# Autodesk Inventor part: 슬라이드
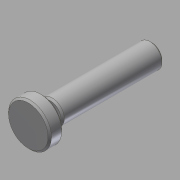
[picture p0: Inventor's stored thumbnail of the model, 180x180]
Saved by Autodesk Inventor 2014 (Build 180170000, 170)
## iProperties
Created: 2015-09
Part Number: 슬라이드
Material: 강철, 연강
Document SubType Name: Modeling
Designer: mduedu
Density: 1 g/cm^3
Appearance: Steel
Author: mduedu
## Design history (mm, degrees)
sketch "스케치1"
  geometry: C1 r 12.5 at (0, 0); 1 further point
  constraints: 1 centre point, 1 coincident
  dimensions: "d0" = 25 diameter of C1
extrude "돌출1" new body sketch "스케치1" distance "d1" = 8; taper "d2" = 0 deg
sketch "스케치2"
  geometry: C1 r 4 at (0, 0); 1 further point
  constraints: 1 centre point, 1 coincident
  dimensions: "d3" = 8 diameter of C1
extrude "돌출2" join sketch "스케치2" distance "d4" = 5; taper "d5" = 0 deg
sketch "스케치3"
  geometry: C1 r 7 at (0, 0); 1 further point
  constraints: 1 centre point, 1 coincident
  dimensions: "d6" = 14 diameter of C1
extrude "돌출3" join sketch "스케치3" distance "d7" = 59; taper "d8" = 0 deg
hole "구멍1" diameter "d11" = 4.134; stored, may be unused: countersink angle "d15" = 90 deg, drill point angle "d17" = 118 deg; dims "d9" = 10, "d10" = 10, "d12" = 9, "d13" = 4, "d14" = 2, "d16" = 12
chamfer "모따기1" distance "d18" = 1; stored, may be unused: second distance "d19" = 2, angle "d20" = 45 deg
node "솔리드1"
